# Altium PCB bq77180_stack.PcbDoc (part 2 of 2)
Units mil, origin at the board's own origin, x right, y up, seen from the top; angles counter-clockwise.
Board outline 2755 x 1574 mil, 2 copper layers (Top Layer, Bottom Layer), stack 30.108 mil thick; 67 components, 47 nets, 175 pads, 125 vias.
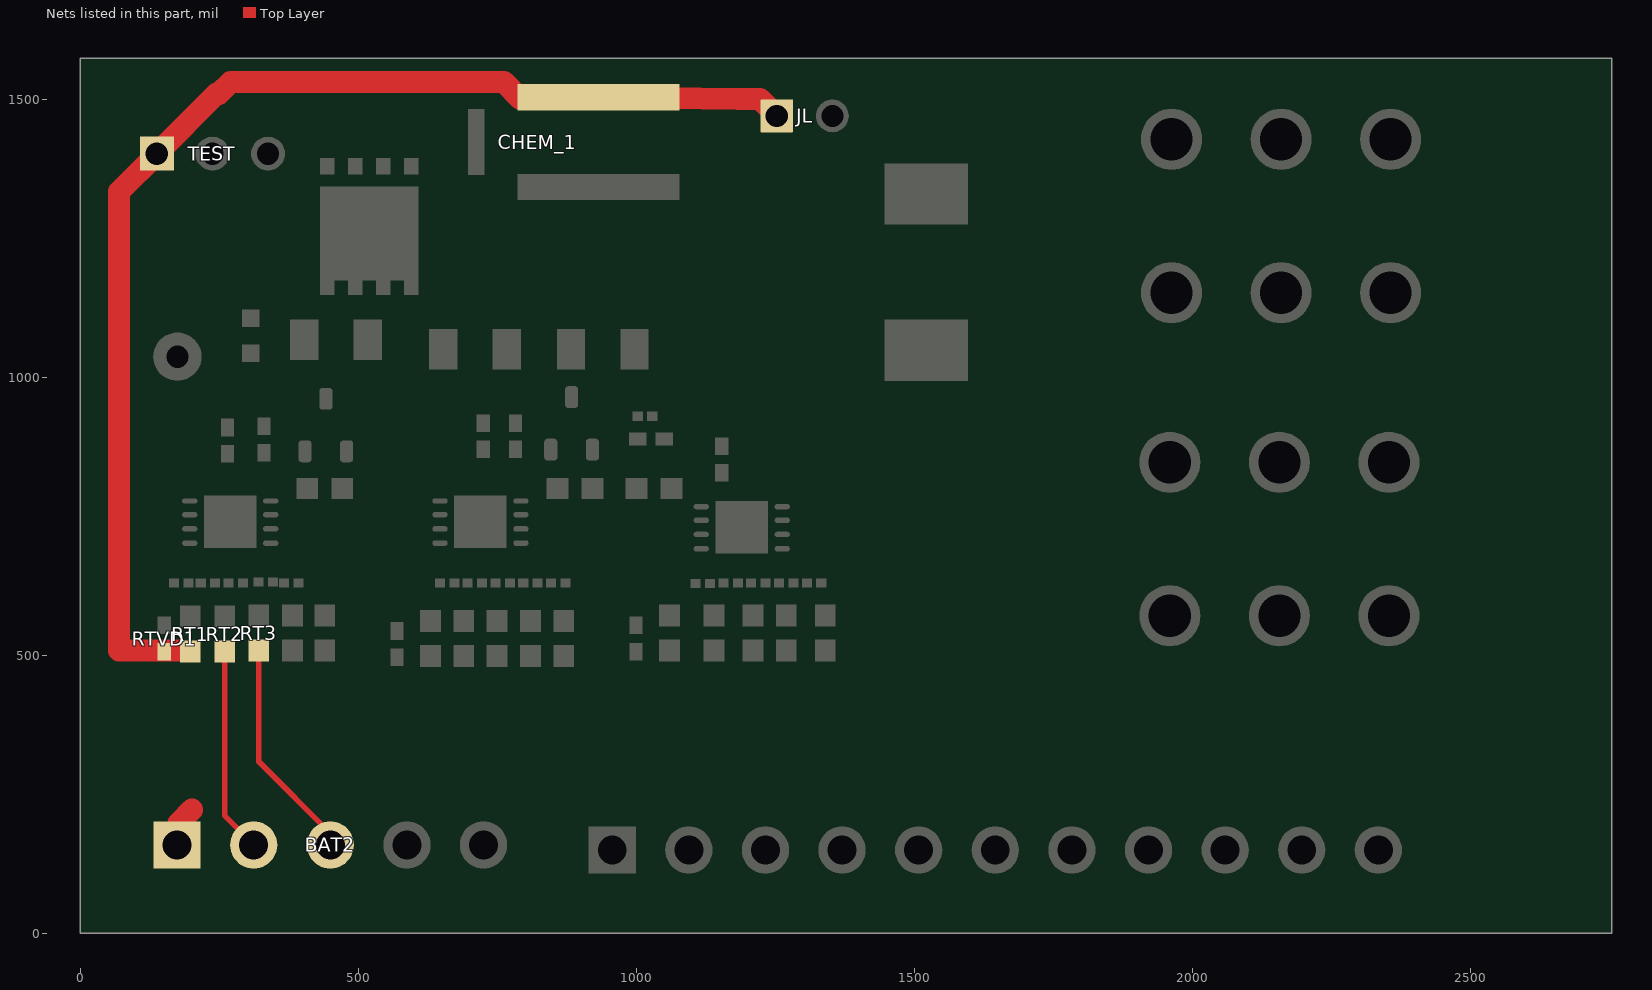
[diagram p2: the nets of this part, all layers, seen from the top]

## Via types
v1: diameter 50, hole 28, Top Layer to Bottom Layer, 108 vias
v2: diameter 19.68, hole 7.87, Top Layer to Bottom Layer, 15 vias
v3: diameter 40, hole 25, Top Layer to Bottom Layer, 2 vias

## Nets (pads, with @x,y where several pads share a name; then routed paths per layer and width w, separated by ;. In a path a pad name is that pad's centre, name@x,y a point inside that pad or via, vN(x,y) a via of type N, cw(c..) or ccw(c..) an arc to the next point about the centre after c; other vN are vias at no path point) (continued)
VC13: BAT2.3 RT3.2 | length 406.3
  Top Layer w10: RT3.2@321.3,508.5 321.3,308.7 453,177 BAT2.3@453,156.8
VC14: BAT2.2 RT2.2 | length 374.4
  Top Layer w10: RT2.2@260,506.5 260,212 BAT2.2@315.2,156.8
  Top Layer w20: RT2.2@260,507.2 RT2.2@261.3,508.5
VSTACK: BAT2.1 CHEM_1.1 JL.1 RT1.2 RTVD1.2 TEST.1 | length 2042.4
  Top Layer w40: TEST.1@138,1402.16 245.84,1510 250,1510 271,1531 762.07,1531 CHEM_1.1@792.36,1500.71 ; TEST.1@139.9,1403.19 138.26,1401.84 70,1333.59 70,508.5 177.41,508.5 ; BAT2.1@177.41,156.8 177.41,198.41 201.3,222.3 ; CHEM_1.1@1050,1502 1183.95,1500.45 1222.55,1500.45 JL.1@1253,1470
copper on no net: | length 69737.8
  Top Layer w1: 13165.46,6954.32 13265.15,7054 13385.15,7174 13505.15,7294 13625.15,7414 13745.15,7534 13865.15,7654 13985.15,7774 ; 13165.46,7014.32 13205.15,7054 13325.15,7174 13445.15,7294 13565.15,7414 13685.15,7534 13805.15,7654 13925.15,7774 ; 13165.46,7074.32 13265.15,7174 13385.15,7294 13505.15,7414 13625.15,7534 13745.15,7654 13865.15,7774 ; 13165.46,7134.32 13205.15,7174 13325.15,7294 13445.15,7414 13565.15,7534 13685.15,7654 13805.15,7774 ; 13165.46,7194.32 13265.15,7294 13385.15,7414 13505.15,7534 13625.15,7654 13745.15,7774 ; 13165.46,7254.32 13205.15,7294 13325.15,7414 13445.15,7534 13565.15,7654 13685.15,7774 ; 13165.46,7314.32 13265.15,7414 13385.15,7534 13505.15,7654 13625.15,7774 ; 13165.46,7374.32 13205.15,7414 13325.15,7534 13445.15,7654 13565.15,7774 ; 13165.46,7434.32 13265.15,7534 13385.15,7654 13505.15,7774 ; 13165.46,7494.32 13205.15,7534 13325.15,7654 13445.15,7774 ; 13165.46,7554.32 13265.15,7654 13385.15,7774 ; 13165.46,7614.32 13205.15,7654 13325.15,7774 ; 13165.46,7674.32 13265.15,7774 ; 13165.46,7734.32 13205.15,7774 ; 13205.15,6934 13325.15,7054 13445.15,7174 13565.15,7294 13685.15,7414 13805.15,7534 13925.15,7654 14045.15,7774 ; 13265.15,6934 13385.15,7054 13505.15,7174 13625.15,7294 13745.15,7414 13865.15,7534 13985.15,7654 14105.15,7774 ; 13325.15,6934 13445.15,7054 13565.15,7174 13685.15,7294 13805.15,7414 13925.15,7534 14045.15,7654 14165.15,7774 ; 13385.15,6934 13505.15,7054 13625.15,7174 13745.15,7294 13865.15,7414 13985.15,7534 14105.15,7654 14225.15,7774 ; 13445.15,6934 13565.15,7054 13685.15,7174 13805.15,7294 13925.15,7414 14045.15,7534 14165.15,7654 14285.15,7774 ; 13505.15,6934 13625.15,7054 13745.15,7174 13865.15,7294 13985.15,7414 14105.15,7534 14225.15,7654 14285.15,7714 ; 13565.15,6934 13685.15,7054 13805.15,7174 13925.15,7294 14045.15,7414 14165.15,7534 14285.15,7654 ; 13625.15,6934 13745.15,7054 13865.15,7174 13985.15,7294 14105.15,7414 14225.15,7534 14285.15,7594 ; 13685.15,6934 13805.15,7054 13925.15,7174 14045.15,7294 14165.15,7414 14285.15,7534 ; 13745.15,6934 13865.15,7054 13985.15,7174 14105.15,7294 14225.15,7414 14285.15,7474 ; 13805.15,6934 13925.15,7054 14045.15,7174 14165.15,7294 14285.15,7414 ; 13865.15,6934 13985.15,7054 14105.15,7174 14225.15,7294 14285.15,7354 ; 13925.15,6934 14045.15,7054 14165.15,7174 14285.15,7294 ; 13985.15,6934 14105.15,7054 14225.15,7174 14285.15,7234 ; 14045.15,6934 14165.15,7054 14285.15,7174 ; 14105.15,6934 14225.15,7054 14285.15,7114 ; 14165.15,6934 14285.15,7054 ; 14225.15,6934 14285.15,6994
  Top Layer w15: 9746.34,7054 10156.26,7054 11086,7054 11945.77,7054 12595.6,7054 13165.46,7054 14285.15,7054 ; 9746.34,7174 10156.26,7174 11086,7174 11945.77,7174 12595.6,7174 13165.46,7174 14285.15,7174 ; 9746.34,7294 10156.26,7294 11086,7294 11945.77,7294 12595.6,7294 13165.46,7294 14285.15,7294 ; 9746.34,7414 10156.26,7414 11086,7414 11945.77,7414 12595.6,7414 13165.46,7414 14285.15,7414 ; 9746.34,7534 10156.26,7534 11086,7534 11945.77,7534 12595.6,7534 13165.46,7534 14285.15,7534 ; 9746.34,7654 10156.26,7654 11086,7654 11945.77,7654 12595.6,7654 13165.46,7654 14285.15,7654 ; 9746.34,7774 14285.15,7774 ; 10156.26,7894 10156.26,6934 ; 11086,7894 11086,6934 ; 11945.77,7894 11945.77,6934 ; 12595.6,7894 12595.6,6934 ; 13165.46,7894 13165.46,6934 ; 10156.26,6934 11086,6934 ; 10156.26,6934 9746.34,6934 9746.34,7894 14285.15,7894 14285.15,6934 13165.46,6934 ; 11086,6934 11945.77,6934 ; 11945.77,6934 12595.6,6934 ; 12595.6,6934 13165.46,6934

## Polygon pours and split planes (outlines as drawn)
VSTACK on Top Layer "VSTACK2PAD" (solid, remove dead copper, pour order 78): 115.9,75.11 251.9,75.11 245.9,81.11 245.9,181.11 245.9,457.13 220.9,482.13 220.9,529.11 84.9,529.11 83.9,530.11 83.9,419.11 83.9,97.11 105.9,75.11 111.9,75.11
"PACK NEG" on Top Layer "PACK_NEG_L01_P020" (solid, remove dead copper, pour order 80): 973,1085.43 973,1137 974,1138 1047.57,1160 1128,1160 1262,1160 1262,950 1229,970 1128,970 1024,970 1024,1012 1023,1013 1022,1014 1022,1086 973,1086 972,1087
NetC1_1 on Top Layer "NETC1_1_L01_P021" (solid, remove dead copper, pour order 79): 1369,1222 1559,1222 1566,1215 1638,1171 1686,1153 1729,1117 1760,1086 1794.5,1051.5 1906,1051.5 1924.5,1051.5 2128,1051.5 2232.5,1051.5 2338,1051.5 2405.5,1051.5 2484,1051.5 2484,1070 2545,1131 2551,1131 2551,1523 2525,1549 2513,1561 1896,1561 1285,1561 1263,1539 1265,1537 1265,1221 1330,1221 1331,1222
"PACK NEG" on Top Layer "PACK_NEG_L01_P023" (solid, remove dead copper, pour order 82): -9.64,-10.63 -9.64,1563.37 2745.36,1563.37 2745.36,-10.63
"PACK NEG" on Bottom Layer "BOT2PACKNEG" (solid, remove dead copper, pour order 84): 61,991 61,1007 61,1021 61,1046 61,1088 61,1159 61,1231 61,1268 36,1293 36,1370 36,1379 36,1401 36,1416 36,1436 191,1497 217,1496 250,1497 316.77,1546.5 804,1555 1383,1555 1738,1555 1738,1497 1738,1481 1738,1177 1738,957.5 1280,967.95 796,979
"PACK NEG" on Bottom Layer "Bottom Layer-TOP HALF" (solid, remove dead copper, pour order 83): 480.13,1145.06 479.76,1147 478.91,1177.97 478.07,1208.91 478.07,1273.5 497,1273.5 501.29,1273.5 501.29,1296.71 497,1431 495.02,1493.03 495.02,1559 1199,1559 1220,1538 1219,1537 1219,1140 1219,977 1208,988 497,988 478.91,1143 477.82,1145.06
"PACK NEG" on Bottom Layer "BottomLayer" (solid, remove dead copper, pour order 85): 0.77,-0.25 0.77,1573.75 2755.77,1573.75 2755.77,-0.25

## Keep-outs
Keep-Out Layer:
  text ".Layer_Name" at 577,-858.49 h60

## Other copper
Top Layer:
  rectangle net "PACK NEG": 494.84,1388 590,1398
  pour cut-out: 125.39,443.88 121,448.27 121,539.73 125.39,544.12 124.36,545.15 49.94,545.15 49.94,449.21 54.28,444.88
  text "Layer" at 9806.34,7804 h60
  text "Name" at 10216.26,7804 h60
  text "Material" at 11146,7804 h60
  text "Thickness" at 12005.77,7804 h60
  text "Constant" at 12655.6,7804 h60
  text "Board Layer Stack" at 13225.46,7804 h60
  text "1" at 9806.34,7684 h60
  text "Top Overlay" at 10216.26,7684 h60
  text "2" at 9806.34,7564 h60
  text "Top Solder" at 10216.26,7564 h60
  text "Solder Resist" at 11146,7564 h60
  text "0.40mil" at 12005.77,7564 h60
  text "3.5" at 12655.6,7564 h60
  text "3" at 9806.34,7444 h60
  text "Top Layer" at 10216.26,7444 h60
  text "Copper" at 11146,7444 h60
  text "2.80mil" at 12005.77,7444 h60
  text "4" at 9806.34,7324 h60
  text "Dielectric1" at 10216.26,7324 h60
  text "FR-4" at 11146,7324 h60
  text "24.51mil" at 12005.77,7324 h60
  text "4.8" at 12655.6,7324 h60
  text "5" at 9806.34,7204 h60
  text "Bottom Layer" at 10216.26,7204 h60
  text "Copper" at 11146,7204 h60
  text "2.80mil" at 12005.77,7204 h60
  text "6" at 9806.34,7084 h60
  text "Bottom Solder" at 10216.26,7084 h60
  text "Solder Resist" at 11146,7084 h60
  text "0.40mil" at 12005.77,7084 h60
  text "3.5" at 12655.6,7084 h60
  text "7" at 9806.34,6964 h60
  text "Bottom Overlay" at 10216.26,6964 h60
  text ".Layer_Name" at 577,-858.49 h60
Bottom Layer:
  text ".Layer_Name" at 577,-858.49 h60

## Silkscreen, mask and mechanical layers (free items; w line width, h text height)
Top Overlay:
  text "VC11" at 681,236 h25
  text "VC15" at 135,233 h25
  text "VC13" at 407,233 h25
  text "VC12" at 538,233 h25
  text "VC10" at 904,233 h25
  text "VC14" at 274,232 h25
  text "VC9" at 1046,232 h25
  text "VC8" at 1191,229 h25
  text "VC7" at 1324,228 h25
  text "VC6" at 1463,226 h25
  text "VC5" at 1603,224 h25
  text "VC4" at 1741,224 h25
  text "VC3" at 1881,223 h25
  text "VC2" at 2017,219 h25
  text "VC1" at 2150,219 h25
  text "GND/PACK -" at 2294,214 h25
  text ".Layer_Name" at 577,-858.49 h60
Bottom Overlay:
  text ".Layer_Name" at 577,-858.49 h60
Top Paste:
  text ".Layer_Name" at 577,-858.49 h60
Bottom Paste:
  text ".Layer_Name" at 577,-858.49 h60
Top Solder:
  text ".Layer_Name" at 577,-858.49 h60
  text ".Layer_Name" at 577,-858.49 h60
Bottom Solder:
  text ".Layer_Name" at 577,-858.49 h60
Drill Guide:
  text ".Layer_Name" at 577,-858.49 h60
M1 Board Outline:
  lines w10: 0,6.69 6.69,0 ; 0,0 0,1574 2755,1574 2755,0 0,0
  text ".Layer_Name" at 577,-858.49 h60
M2 Board Dimensions:
  rectangle: 0,-275 125,-150
  rectangle: 125,-400 500,-275
  lines w7: 0,-275 1000,-275 ; 125,-400 125,-150 ; 250,-400 250,-150 ; 500,-400 500,-150 ; 750,-400 750,-150 ; 0,-400 1000,-400 1000,-150 0,-150 0,-400
  lines w10: 2.87,-52 3.13,-32 ; 62.73,-62.78 3,-42 ; 63.26,-22.79 3,-42 ; 984.66,-54.83 3,-42 ; 1776.34,-65.17 2758,-78 ; 2697.74,-97.21 2758,-78 ; 2698.27,-57.22 2758,-78 ; 2757.87,-88 2758.13,-68 ; 2829.3,1514.9 2849,1575 ; 2836.7,55.9 2857,-4 ; 2839,1574.95 2859,1575.05 ; 2847,-4.05 2867,-3.95 ; 2851.17,1146.38 2849,1575 ; 2854.83,424.62 2857,-4 ; 2869.3,1515.1 2849,1575 ; 2876.7,56.1 2857,-4
  text "1579.02 (mil)" at 2815.23,1136.2 h60 r270.29
  text "2755.235 (mil)" at 994.19,-90.95 h60 r359.25
  text ".Layer_Name" at 577,-858.49 h60
M3 3D STEP Top:
  text ".Layer_Name" at 577,-858.49 h60
M4 3D STEP Bottom:
  text ".Layer_Name" at 577,-858.49 h60
M5 Assembly Top:
  lines w10: -292,-930.17 6308,-930.17 ; -292,-726.83 6310,-726.83 ; -292,-523.5 -292,-1133.5 3713,-1133.5 6310,-1133.5 6310,-523.5 -291.5,-523.5 -291.5,-1133.5 1284,-1133.5 ; 2173,-1133.5 2173,-523.5 ; 3440,-726.83 3440,-523.5 ; 4280,-726.83 4280,-523.5 ; 4902,-1140 4902,-937.17
  text "COMPONENTS MARKED 'DNP' SHOULD NOT BE POPULATED." at 1153.5,-318.5 h60
  text "ASSEMBLY VARIANT:" at 1153,-434 h60
  text ".VariantName" at 2189,-434 h60
  text "PCB VIEWED FROM TOP SIDE" at -228.5,-655.67 h60
  text "BOARD #:" at 2248,-655.67 h60
  text ".PRJ_Number" at 2793.5,-655.67 h60
  text "REV:" at 3638,-655.67 h60
  text ".PCB_Rev" at 3929.5,-655.67 h60
  text "SVN REV:" at 4476,-655.67 h60
  text ".VersionControl_RevNumber" at 4982,-655.67 h60
  text "TID #:" at 2248,-859 h60
  text ".TID" at 2793.5,-859 h60
  text "PLOT NAME =" at -228.5,-1064.34 h60
  text ".plot_File_Name" at 577,-1064.34 h60
  text "GENERATED    :" at 2250,-1064.34 h60
  text ".Print_Date" at 3119.5,-1064.34 h60
  text ".Print_Time" at 3848.5,-1064.34 h60
  text "TEXAS INSTRUMENTS" at 5113,-1064.34 h60
M6 Assembly Bottom:
  lines w10: -292.5,-727.33 6309.5,-727.33 ; -290.5,-930.67 6309.5,-930.67 ; 1115.5,-1140.5 1115.5,-937.67 ; 1737.5,-727.33 1737.5,-524 ; 2577.5,-727.33 2577.5,-524 ; 3844.5,-1134 3844.5,-524 ; 4733.5,-1134 6309,-1134 6309,-524 -292.5,-524 -292.5,-1134 2304.5,-1134 6309.5,-1134 6309.5,-524
  text "COMPONENTS MARKED 'DNP' SHOULD NOT BE POPULATED." at 6102,-318 h60
  text ".VariantName" at 5058,-434 h60
  text "ASSEMBLY VARIANT:" at 6097,-434 h60
  text ".VersionControl_RevNumber" at 1035.5,-656.17 h60
  text "SVN REV:" at 1541.5,-656.17 h60
  text ".PCB_Rev" at 2088,-656.17 h60
  text "REV:" at 2379.5,-656.17 h60
  text ".PRJ_Number" at 3224,-656.17 h60
  text "BOARD #:" at 3769.5,-656.17 h60
  text "PCB VIEWED FROM BOTTOM SIDE" at 6246,-656.17 h60
  text ".TID" at 3224,-859.5 h60
  text "TID #:" at 3769.5,-859.5 h60
  text "TEXAS INSTRUMENTS" at 904.5,-1064.84 h60
  text ".Print_Time" at 2169,-1064.84 h60
  text ".Print_Date" at 2898,-1064.84 h60
  text "GENERATED    :" at 3767.5,-1064.84 h60
  text ".plot_File_Name" at 5440.5,-1064.84 h60
  text "PLOT NAME =" at 6246,-1064.84 h60
M9 Title Sheet:
  drawing of 57 lines, arcs and shapes, not listed
  text "1" at 739.84,8036.5 h70
  text "2" at 3235.5,8036.5 h70
  text "3" at 5724.84,8036.5 h70
  text "4" at 8231.51,8036.5 h70
  text "5" at 10730.5,8036.5 h70
  text "6" at 13235.5,8036.5 h70
  text "A" at -416.5,6893.5 h70
  text "A" at 14383.5,6893.5 h70
  text "B" at -416.5,4513.5 h70
  text "B" at 14383.5,4513.5 h70
  text "C" at -416.5,2138.5 h70
  text "C" at 14383.5,2138.5 h70
  text "PROJECT TITLE:" at 11343.5,277.5 h45
  text "75V Stack Protector using 3X- bq77180" at 11393.5,144.17 h70
  text "DESIGNED FOR:" at 11343.5,-23.5 h45
  text "TIDA-00108" at 11393.5,-163.5 h70
  text "D" at -416.5,-231.5 h70
  text "D" at 14383.5,-231.5 h70
  text "FILE NAME:" at 11343.5,-323.5 h45
  text "bq77180_stack.PcbDoc" at 11393.5,-443.5 h70
  text "Texas Instruments (TI) and/or its licensors do not warrant the accuracy or completeness of this specification" at 6374,-605.34 h45
  text "ENGINEER:" at 11343.5,-613.5 h45
  text "LAYOUT BY:" at 12848.5,-613.5 h45
  text "or any information contained therein. TI and/or its licensors do not warrant that this design will meet" at 6329.01,-718 h45
  text "Vish Nadarajah" at 11393.5,-768.49 h70
  text "Vish Nadarajah" at 12899,-768.49 h70
  text "the specifications, will be suitable for your application or fit for any particular purpose, or will operate in" at 6329.01,-830.67 h45
  text ".Layer_Name" at 577,-858.49 h60
  text "ALTIUM DESIGNER VERSION:" at 12848.5,-923.5 h45
  text "an implementation. TI and/or its licensors do not warrant that the design is production worthy. You should" at 6329.01,-943.33 h45
  text "completely validate and test your design implementation to confirm the system functionality for your application." at 6374,-1056 h45
  text ".print_Scale" at 11393.5,-1056.83 h70
  text "16.1.11" at 12899,-1056.83 h70
  text "1" at 739.84,-1263.5 h70
  text "2" at 3235.5,-1263.5 h70
  text "3" at 5724.84,-1263.5 h70
  text "4" at 8231.51,-1263.5 h70
  text "5" at 10730.5,-1263.5 h70
  text "6" at 13235.5,-1263.5 h70
M10 Fab Notes:
  drawing of 173 lines, arcs and shapes, not listed
  text "DESIGN INFORMATION" at 12378.02,6201 h60
  text "MIN. TRACK WIDTH:" at 11733.46,6021 h60
  text "8" at 12829.7,6021 h60
  text "MIL" at 12984.46,6021 h60
  text "MIN. CLEARANCE:" at 11733.46,5889 h60
  text "0.2" at 12769.7,5889 h60
  text "mm" at 12984.46,5889 h60
  text "MIN. VIA PAD SIZE:" at 11733.46,5757 h60
  text "24" at 12799.71,5757 h60
  text "MIL" at 12984.46,5757 h60
  text "0.05mm (2MIL)" at 12428.46,5615.29 h60
  text "MINIMUM ANNULAR RING" at 11404.23,5611 h60
  text "EXTERNAL" at 13136.46,5611 h60
  text "PER" at 11604.23,5493 h60
  text "IPC-D-275 CLASS 2 LEVEL C" at 11824.23,5493 h60
  text "MIL, HOLES" at 13312.46,5380.71 h60
  text "+/-" at 12920,5380 h60
  text "+/-" at 13774,5380 h60
  text "REGISTRATION TOLERANCES:" at 11404.23,5375 h60
  text "METAL" at 12604,5375 h60
  text "5" at 13180.2,5375 h60
  text "3" at 14013.2,5375 h60
  text "MIL" at 14129.46,5375 h60
  text "+/-" at 13774,5262 h60
  text "HOLE SIZE TOLERANCE (UNLESS OTHERWISE SPECIFIED):" at 11404.23,5257 h60
  text "3" at 14013.2,5257 h60
  text "MIL" at 14129.46,5257 h60
  text "MATERIAL:" at 11329.46,5047.54 h60
  text "FR-4 High Tg" at 12315.9,4907.21 h60
  text "FR-408" at 11750.46,4898.64 h60
  text "OTHER" at 13238.46,4898.64 h60
  text "X" at 12161,4895 h60
  text "62 MIL (1.6mm) +/-10%" at 12070.56,4735.92 h60
  text "THICKNESS:" at 11404.23,4731.64 h60
  text "X" at 11942.4,4731.64 h60
  text "OTHER" at 13355.46,4731.64 h60
  text "TOLERANCE:" at 11404.23,4573.64 h60
  text "X" at 12243.53,4573.64 h60
  text "ANSI IPC-6012 TYPE 3 CLASS 2" at 12430.48,4573.64 h60
  text "OTHER +/-" at 12430.46,4417.64 h60
  text "BOW & TWIST:" at 11404.23,4260.64 h60
  text "X" at 12243.53,4260.64 h60
  text "ANSI IPC-6012 TYPE 3 CLASS 2" at 12430.48,4260.64 h60
  text "OTHER +/-" at 12430.46,4102.13 h60
  text "DRILLING:" at 11329.46,3963.64 h60
  text "REFERENCE:" at 11404.23,3846.64 h60
  text "X" at 12052.46,3846.64 h60
  text "AS SHOWN" at 12239.46,3846.64 h60
  text "X" at 12953.46,3846.64 h60
  text "NC_DRILL FILES" at 13090.46,3846.64 h60
  text "PTH COPPER THICKNESS:" at 11404.23,3688.64 h60
  text "X" at 12534.46,3688.64 h60
  text "20-30 um" at 12671.46,3688.64 h60
  text "OTHER" at 13388.46,3688.64 h60
  text "BOARD FINISH:" at 11329.46,3529.64 h60
  text "SILKSCREEN:" at 11484.68,3411.64 h60
  text "X" at 12433.46,3411.64 h60
  text "TOP" at 12559.46,3411.64 h60
  text "X" at 12943.46,3411.64 h60
  text "BOTTOM" at 13070.46,3411.64 h60
  text "SILKSCREEN COLOR:" at 11484.68,3244.64 h60
  text "X" at 12432.42,3244.64 h60
  text "WHITE" at 12559.46,3244.64 h60
  text "OTHER" at 13070.46,3244.64 h60
  text "X" at 12563.42,3085.44 h60
  text "GREEN" at 12690.46,3085.44 h60
  text "OTHER" at 13308.46,3085.44 h60
  text "SOLDER RESIST COLOR:" at 11484.68,3074.64 h60
  text "X" at 12563.42,2915.44 h60
  text "MATTE" at 12690.46,2915.44 h60
  text "SEMI-GLOSS" at 13308,2914.8 h60
  text "IMMERSION GOLD (ENIG)" at 12390.46,2726.92 h60
  text "ENEPIG" at 13728,2723.64 h60
  text "SURFACE FINISH:" at 11329.46,2722.64 h60
  text "X" at 12203.51,2722.64 h60
  text "IMM. TIN/SILVER OR EQUIV" at 11659,2565.64 h60
  text "OTHER" at 13090.46,2565.64 h60
  text "ARRAY/PANEL:" at 11329.46,2386.64 h60
  text "CUT AND TRIM PER M1 BOARD OUTLINE" at 12390.46,2382.35 h60
  text "N.C. ROUTE" at 12390.46,2230.64 h60
  text "X" at 13069.46,2230.64 h60
  text "V. SCORE" at 13256.46,2230.64 h60
  text "CERTIFICATION:" at 11329.46,2093.64 h60
  text "MATERIALS AND WORKMANSHIP FOR ALL PCBS" at 12054.46,2093.64 h60
  text "TO MEET OR EXCEED THE REQUIREMENTS OF:" at 12054.46,1995.64 h60
  text "X" at 11680.96,1859.13 h60
  text "ANSI IPC-A-600F CLASS ->" at 11819.96,1859.13 h60
  text "X" at 13459.02,1859.13 h60
  text "2" at 13577.96,1859.14 h60
  text "1" at 13262.96,1857.64 h60
  text "3" at 13931.96,1857.64 h60
  text "X" at 12495.02,1699.64 h60
  text "RoHS" at 12631.96,1699.64 h60
  text "OTHER" at 13276.36,1699.64 h60
  text "PER ORDER" at 13673.42,1699.64 h60
  text "ALL BOARDS MUST MEET OR EXCEED UL94-V0 REQUIREMENTS." at 11357,1534 h60
  text "PCB MUST BEAR THE UL94V-0 UL REGISTERED MATERIAL ID NUMBER" at 11357,1414 h60
  text "ADDITIONAL REQUIREMENTS:" at 11329.46,1240.64 h60
  text "MICROSECTION:" at 11404.23,1125.64 h60
  text "YES" at 12309.96,1125.64 h60
  text "REQUIRED" at 13171.46,969.49 h60
  text "BARE BOARD ELEC. TEST:" at 11404.23,966.64 h60
  text "NONE" at 12709.96,966.64 h60
  text "X" at 13044.46,966.64 h60
  text "PER ORDER" at 13763.46,966.64 h60
  text ".Layer_Name" at 577,-858.49 h60
M11 Gerber Information:
  lines w10: -292,-930.17 6308,-930.17 ; -292,-726.83 6310,-726.83 ; -292,-523.5 -292,-1133.5 3713,-1133.5 6310,-1133.5 6310,-523.5 -291.5,-523.5 -291.5,-1133.5 1284,-1133.5 ; 2173,-1133.5 2173,-523.5 ; 3440,-726.83 3440,-523.5 ; 4280,-726.83 4280,-523.5 ; 4902,-1140 4902,-937.17
  text "ALL ARTWORK VIEWED FROM TOP SIDE" at -228.5,-655.67 h60
  text "BOARD #:" at 2248,-655.67 h60
  text ".PRJ_Number" at 2793.5,-655.67 h60
  text "REV:" at 3638,-655.67 h60
  text ".PCB_Rev" at 3929.5,-655.67 h60
  text "SVN REV:" at 4476,-655.67 h60
  text ".VersionControl_RevNumber" at 4982,-655.67 h60
  text "LAYER NAME =" at -228.5,-858.49 h60
  text "TID #:" at 2248,-859 h60
  text ".TID" at 2793.5,-859 h60
  text "PLOT NAME =" at -228.5,-1064.34 h60
  text ".plot_File_Name" at 577,-1064.34 h60
  text "GENERATED    :" at 2250,-1064.34 h60
  text ".Print_Date" at 3119.5,-1064.34 h60
  text ".Print_Time" at 3848.5,-1064.34 h60
  text "TEXAS INSTRUMENTS" at 5113,-1064.34 h60
M12 Stackup:
  drawing of 191 lines, arcs and shapes, not listed
  text "Layer" at 9790.34,7830 h60
  text "Name" at 10200.26,7830 h60
  text "Material" at 11130,7830 h60
  text "Thickness" at 11989.77,7830 h60
  text "Constant" at 12639.6,7830 h60
  text "Board Layer Stack" at 13209.46,7830 h60
  text "1" at 9790.34,7710 h60
  text "Top Overlay" at 10200.26,7710 h60
  text "2" at 9790.34,7590 h60
  text "Top Solder" at 10200.26,7590 h60
  text "Solder Resist" at 11130,7590 h60
  text "0.40mil" at 11989.77,7590 h60
  text "3.5" at 12639.6,7590 h60
  text "3" at 9790.34,7470 h60
  text "Top Layer" at 10200.26,7470 h60
  text "Copper" at 11130,7470 h60
  text "1.40mil" at 11989.77,7470 h60
  text "4" at 9790.34,7350 h60
  text "Dielectric1" at 10200.26,7350 h60
  text "FR-4" at 11130,7350 h60
  text "59.20mil" at 11989.77,7350 h60
  text "4.8" at 12639.6,7350 h60
  text "5" at 9790.34,7230 h60
  text "Bottom Layer" at 10200.26,7230 h60
  text "Copper" at 11130,7230 h60
  text "1.40mil" at 11989.77,7230 h60
  text "6" at 9790.34,7110 h60
  text "Bottom Solder" at 10200.26,7110 h60
  text "Solder Resist" at 11130,7110 h60
  text "0.40mil" at 11989.77,7110 h60
  text "3.5" at 12639.6,7110 h60
  text "7" at 9790.34,6990 h60
  text "Bottom Overlay" at 10200.26,6990 h60
  text ".Layer_Name" at 577,-858.49 h60
M13 Component Bodies Top:
  text ".Layer_Name" at 577,-858.49 h60
M14 Component Bodies Bottom:
  text ".Layer_Name" at 577,-858.49 h60
M15 Courtyards Top:
  text ".Layer_Name" at 577,-858.49 h60
M16 Courtyards Bottom:
  text ".Layer_Name" at 577,-858.49 h60
Drill Drawing:
  circle w10: c3483.72,943.32 r16.58
  circle w10: c3483.72,943.32 r27.63
  lines w10: 3456.09,1053.83 3469.9,1053.83 3469.9,1040.02 3497.53,1040.02 3497.53,1053.83 3511.34,1053.83 3511.34,1081.46 3497.53,1081.46 3497.53,1095.27 3469.9,1095.27 3469.9,1081.46 3456.09,1081.46 3456.09,1053.83 ; 3456.09,1178.15 3469.9,1178.15 3483.72,1164.34 3497.53,1178.15 3511.34,1178.15 3497.53,1191.96 3511.34,1205.78 3497.53,1205.78 3483.72,1219.59 3469.9,1205.78 3456.09,1205.78 3469.9,1191.96 3456.09,1178.15 ; 3467.14,1059.35 3475.43,1059.35 3475.43,1051.07 3492.01,1051.07 3492.01,1059.35 3500.29,1059.35 3500.29,1075.93 3492.01,1075.93 3492.01,1084.22 3475.43,1084.22 3475.43,1075.93 3467.14,1075.93 3467.14,1059.35 ; 3467.14,1183.67 3475.43,1183.67 3483.72,1175.39 3492.01,1183.67 3500.29,1183.67 3492.01,1191.96 3500.29,1200.25 3492.01,1200.25 3483.72,1208.54 3475.43,1200.25 3467.14,1200.25 3475.43,1191.96 3467.14,1183.67
  lines w12: 3406,505.44 6637.49,505.44 ; 3406,1375.68 6637.49,1375.68 ; 3743.86,381.12 3743.86,1500 ; 4075.86,381.12 4075.86,1500 ; 4712.43,381.12 4712.43,1500 ; 4971.57,381.12 4971.57,1500 ; 5346.72,381.12 5346.72,1500 ; 6071.05,381.12 6071.05,1500 ; 3406,381.12 6637.49,381.12 6637.49,1500 3406,1500 3406,381.12
  text "Symbol" at 3480.59,1412.98 h72
  text "Quantity" at 3781.16,1412.98 h72
  text "Finished Hole Size" at 4113.16,1412.98 h72
  text "Plated" at 4749.72,1412.98 h72
  text "Hole Type" at 5008.86,1412.98 h72
  text "Drill Layer Pair" at 5384.02,1412.98 h72
  text "Hole Tolerance" at 6108.35,1412.98 h72
  text "15" at 3781.16,1288.66 h60
  text "7.87mil (0.200mm)" at 4113.16,1288.66 h60
  text "PTH" at 4749.72,1288.66 h60
  text "Round" at 5008.86,1288.66 h60
  text "Top Layer - Bottom Layer" at 5384.02,1288.66 h60
  text "B" at 3455.31,1278.66 h55.25
  text "2" at 3781.16,1164.34 h60
  text "25.00mil (0.635mm)" at 4113.16,1164.34 h60
  text "PTH" at 4749.72,1164.34 h60
  text "Round" at 5008.86,1164.34 h60
  text "Top Layer - Bottom Layer" at 5384.02,1164.34 h60
  text "108" at 3781.16,1040.02 h60
  text "28.00mil (0.711mm)" at 4113.16,1040.02 h60
  text "PTH" at 4749.72,1040.02 h60
  text "Round" at 5008.86,1040.02 h60
  text "Top Layer - Bottom Layer" at 5384.02,1040.02 h60
  text "3" at 3781.16,915.7 h60
  text "40.00mil (1.016mm)" at 4113.16,915.7 h60
  text "PTH" at 4749.72,915.7 h60
  text "Round" at 5008.86,915.7 h60
  text "Top Layer - Bottom Layer" at 5384.02,915.7 h60
  text "3" at 3781.16,791.38 h60
  text "40.16mil (1.020mm)" at 4113.16,791.38 h60
  text "PTH" at 4749.72,791.38 h60
  text "Round" at 5008.86,791.38 h60
  text "Top Layer - Bottom Layer" at 5384.02,791.38 h60
  text "E" at 3455.31,781.39 h55.25
  text "16" at 3781.16,667.06 h60
  text "52.00mil (1.321mm)" at 4113.16,667.06 h60
  text "PTH" at 4749.72,667.06 h60
  text "Round" at 5008.86,667.06 h60
  text "Top Layer - Bottom Layer" at 5384.02,667.06 h60
  text "C" at 3455.31,657.07 h55.25
  text "12" at 3781.16,542.74 h60
  text "76.00mil (1.930mm)" at 4113.16,542.74 h60
  text "PTH" at 4749.72,542.74 h60
  text "Round" at 5008.86,542.74 h60
  text "Top Layer - Bottom Layer" at 5384.02,542.74 h60
  text "D" at 3455.31,532.74 h55.25
  text "159 Total" at 3781.16,418.42 h60
  text ".Layer_Name" at 577,-858.49 h60
M17 Embedded Cavity:
  text ".Layer_Name" at 577,-858.49 h60
M18 Embedded Assembly:
  text ".Layer_Name" at 577,-858.49 h60
M19 Embedded Keepout:
  text ".Layer_Name" at 577,-858.49 h60

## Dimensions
0,-400 to 1000,-400 on M2 Board Dimensions
0,0 to 0,1574 on M2 Board Dimensions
